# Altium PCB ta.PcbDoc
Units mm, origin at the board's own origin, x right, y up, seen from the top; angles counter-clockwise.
Board outline 41.15 x 64.9 mm, 2 copper layers (Top Layer, Bottom Layer); 9 components, 15 nets, 58 pads, 0 vias.
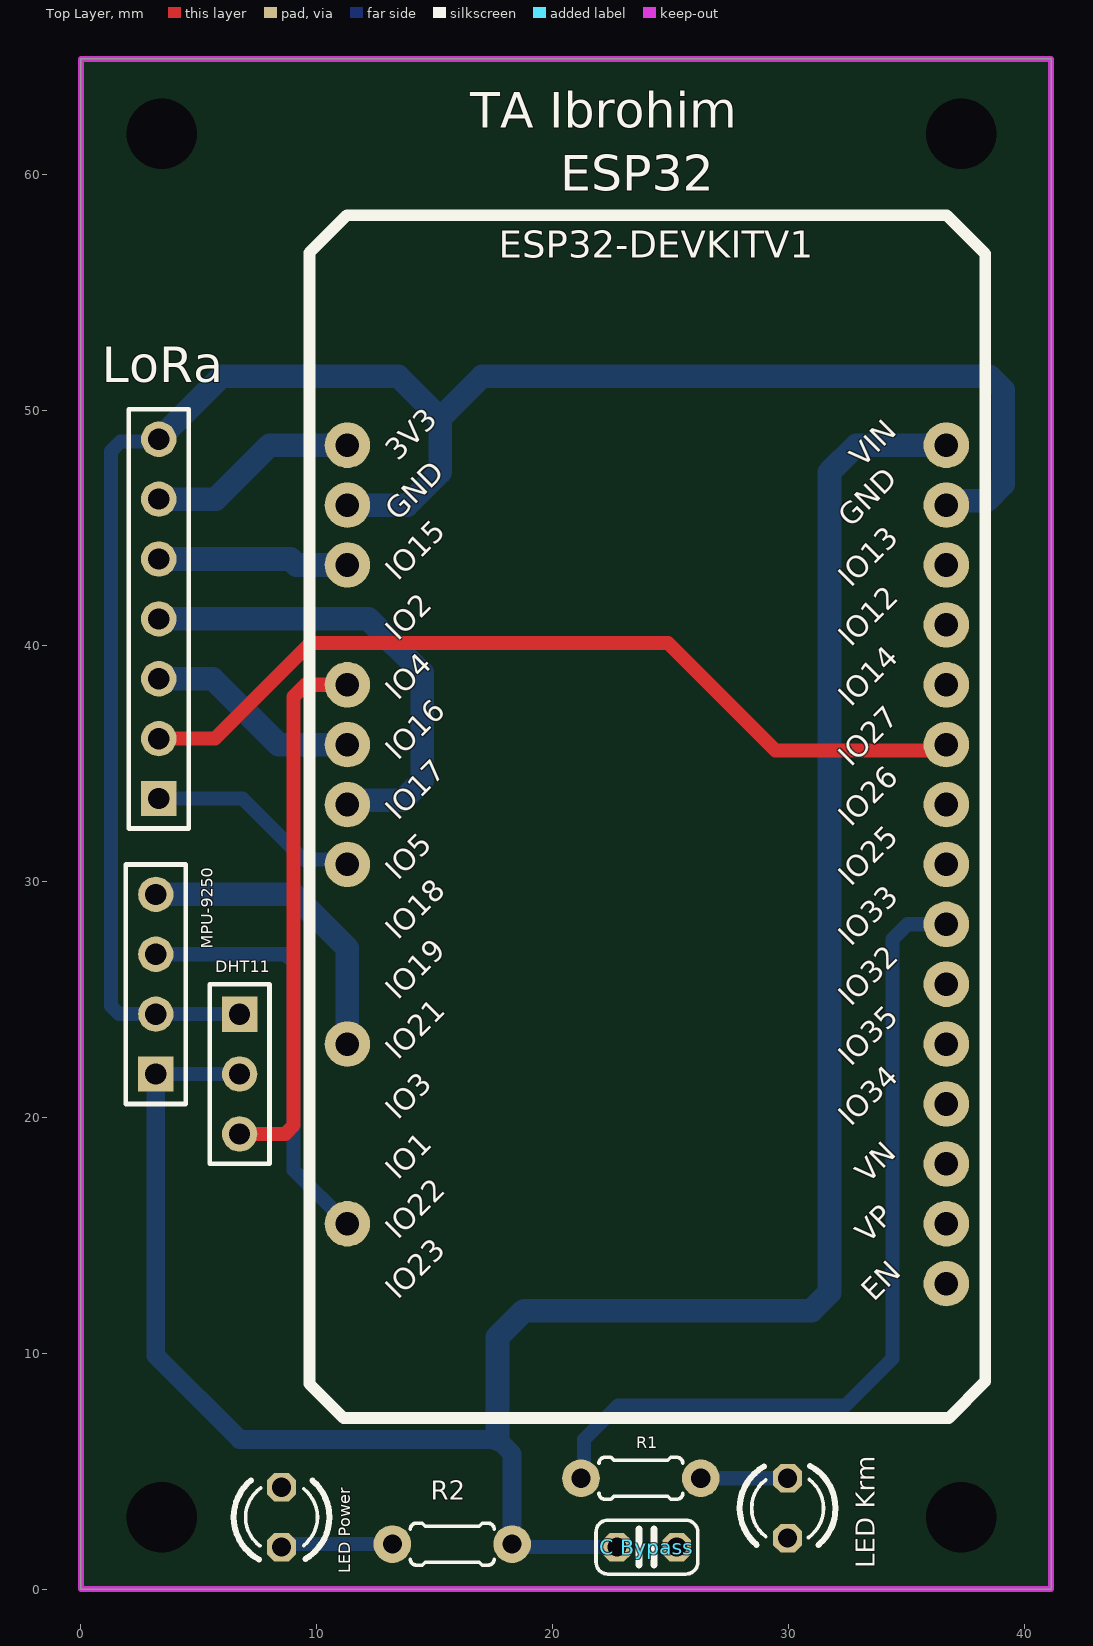
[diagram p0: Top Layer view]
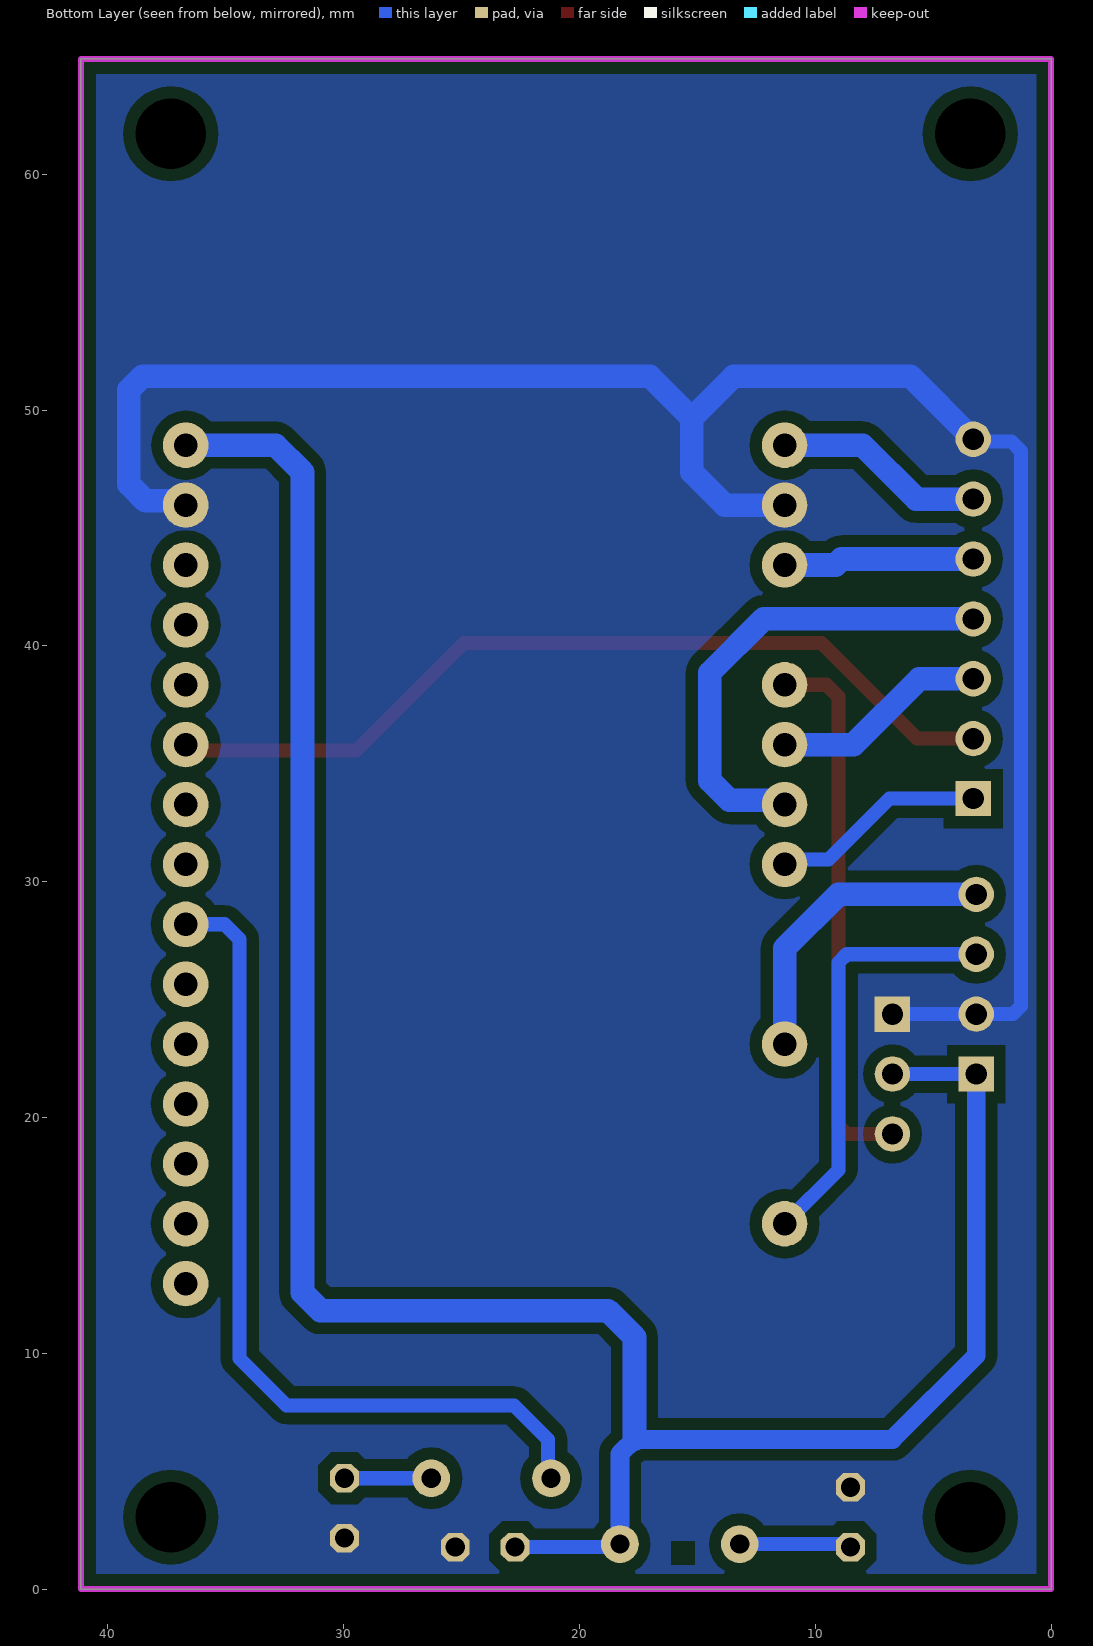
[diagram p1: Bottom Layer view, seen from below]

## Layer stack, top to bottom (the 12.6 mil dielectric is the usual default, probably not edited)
Top Solder: solder mask 0.0102, Solder Resist, Dk 3.5
Top Layer: signal copper 0.0356
Dielectric 1: dielectric 0.32, FR-4, Dk 4.8
Bottom Layer: signal copper 0.0356
Bottom Solder: solder mask 0.0102, Solder Resist, Dk 3.5

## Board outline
0,0 41.148,0 41.148,64.897 0,64.897

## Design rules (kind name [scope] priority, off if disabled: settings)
Clearance [All] p1: gap=0.5 ignorepadtopadclearanceinfootprint=FALSE
HoleSize [All] p1: absolutevalues=TRUE maxlimit=3 minlimit=0.025 maxpercent=80.000 minpercent=20.000
PlaneConnect [All] p1: planeconnectstyle=Direct reliefexpansion=0.508 reliefentries=4 reliefconductorwidth=0.254 reliefairgap=0.254
PolygonConnect [All] p1: connectstyle=Direct reliefconductorwidth=0.254 reliefentries=4 polygonreliefangle="90 Angle" airgapwidth=0.254
RoutingVias [All] p1: holewidth=0.711 width=1.27 viastyle="Through Hole" minholewidth=0.711 minwidth=1.27 maxholewidth=0.711 maxwidth=1.27
SilkToSilkClearance [All] p1: silktosilkclearance=0.104
SilkToSolderMaskClearance [IsPad] p1: minsilkscreentomaskgap=0.104 clearancetoexposedcopper=TRUE
SolderMaskExpansion [All] p1: expansion=0.102 istentingtop=FALSE
Width [All] p1: maxlimit=1.5 minlimit=0.5 preferedwidth=1
26 further rules are at their usual default settings.

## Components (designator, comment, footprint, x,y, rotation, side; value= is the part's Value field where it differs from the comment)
"C Bypass" "100nF" C025-024X044 24.003,1.778 r180 top
DHT11 "DHT11" HDR1X3 6.731,24.384 r270 top
ESP32 "ESP32-DEVKITC-32D" MODULE_ESP32-DEVKITV1 24.003,33.514 r0 top
"LED Krm" "LED Radial" LED3MM 29.972,3.429 r270 top (schematic designator "LED Kirim")
"LED Power" "LED Radial" LED3MM 8.509,3.048 r90 top
LoRa "Header 7" HDR1X7 3.302,33.528 r90 top
MPU-9250 "Header 4" HDR1X4 3.175,21.844 r90 top
R1 "330" 0204/5 23.749,4.699 r0 top
R2 "330" 0204/5 15.748,1.905 r180 top

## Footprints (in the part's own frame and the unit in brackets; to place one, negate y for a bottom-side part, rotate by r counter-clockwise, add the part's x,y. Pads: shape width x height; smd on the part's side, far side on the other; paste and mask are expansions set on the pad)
0204/5 [mm]
  round 1.6 hole 0.813: 1(-2.54,0) 2(2.54,0)
  silkscreen extent -1.78,-0.89 1.78,0.89, body extent -3.22,-0.88 3.23,0.89, height 1.76
C025-024X044 [mil]
  oct 48x48 hole 32: 1(-50,0) 2(50,0)
  silkscreen extent -85,-45 85,45, body extent -93,-49 93,49, height 242
HDR1X3 [mm] "Connector; Header; 3 Position"
  rect 1.5x1.5 hole 0.9: 1(0,0)
  round 1.5 hole 0.9: 2(2.54,0) 3(5.08,0)
  silkscreen extent -1.27,-1.27 6.35,1.27
HDR1X4 [mm] "Connector; Header; 4 Position"
  rect 1.5x1.5 hole 0.9: 1(0,0)
  round 1.5 hole 0.9: 2(2.54,0) 3(5.08,0) 4(7.62,0)
  silkscreen extent -1.27,-1.27 8.89,1.27
HDR1X7 [mm] "Connector; Header; 7 Position"
  rect 1.5x1.5 hole 0.9: 1(0,0)
  round 1.5 hole 0.9: 2(2.54,0) 3(5.08,0) 4(7.62,0) 5(10.16,0) 6(12.7,0) 7(15.24,0)
  silkscreen extent -1.27,-1.27 16.51,1.27
LED3MM [mil]
  oct 48x48 hole 32: 1(-50,0) 2(50,0)
  silkscreen extent -71,-80 61,80
MODULE_ESP32-DEVKITV1 [mil]
  round 76 / inner round 60 / far side round 76 hole 39.37: 1(-500,590.55) 2(-500,490.55) 3(-500,390.55) 6(-500,90.55) 7(-500,-9.45) 11(-500,-409.45) 14(-500,-709.45) 16(500,-809.45) 17(500,-709.45) 18(500,-609.45) 19(500,-509.45) 20(500,-409.45) 21(500,-309.45) 22(500,-209.45) 23(500,-109.45) 24(500,-9.45) 25(500,90.55) 26(500,190.55) 27(500,290.55) 28(500,390.55) 29(500,490.55) 30(500,590.55)
  round 76 on Top Paste: 4(-500,290.55) 9(-500,-209.45) 10(-500,-309.45) 15(-500,-809.45)
  round 76 hole 39.37: 5(-500,190.55) 8(-500,-109.45)
  round 0 all layers, no hole: 12(-500,-509.45) 13(-500,-609.45)
  silkscreen extent -563,-1034 565,974, body extent -560,-1027 562,978, height 283

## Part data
"C Bypass": library part Cap, "Cap Nonpolar (Pad-length X width)"
DHT11: library part "Header 3", "Header, 3-Pin"
ESP32: "Eval Board For Esp-Wroom-32", Package=None
LoRa: "Header, 7-Pin"
MPU-9250: "Header, 4-Pin"
R1 R2: library part "Res 0204", "Resistor 0204"

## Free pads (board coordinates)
  round 0 hole 3: 2(3.429,3.048) 3(37.338,3.048) 4(37.338,61.722) 5(3.429,61.722)

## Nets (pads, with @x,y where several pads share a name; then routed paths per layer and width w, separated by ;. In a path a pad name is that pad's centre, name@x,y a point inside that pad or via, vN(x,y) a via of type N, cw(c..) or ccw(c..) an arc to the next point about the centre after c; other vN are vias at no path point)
3v: ESP32.1 LoRa.6 | length 9.1
  Bottom Layer w1: LoRa.6@3.393,46.137 LoRa.6 5.715,46.228 8.001,48.514 ESP32.1 ESP32.1@11.352,48.465
AUX: ESP32.3 LoRa.5 | length 8.2
  Bottom Layer w1: LoRa.5 8.89,43.688 9.144,43.434 ESP32.3 ESP32.3@11.251,43.486
D13: ESP32.28
GND: "C Bypass.1" "LED Krm.2" "LED Power.2" DHT11.1 ESP32.2 ESP32.29 LoRa.7 MPU-9250.2 | length 83.8
  Bottom Layer w0.6: 3.13,36.24 3.302,36.068 ; LoRa.7@3.206,48.672 1.682,48.672 1.27,48.26 1.27,24.735 1.621,24.384 DHT11.1
  Bottom Layer w1: LoRa.7@3.206,48.672 LoRa.7 5.969,51.435 13.462,51.435 15.24,49.657 ; ESP32.2 13.843,45.974 15.24,47.371 15.24,49.657 ; ESP32.29 36.881,46.152 38.405,46.152 39.116,46.863 39.116,50.854 38.53,51.44 17.023,51.44 15.24,49.657
M0: ESP32.8 LoRa.1 | length 9.2
  Bottom Layer w0.6: LoRa.1 6.858,33.528 9.438,30.948 11.089,30.948 ESP32.8
M1: ESP32.25 LoRa.2 | length 37.1
  Top Layer w0.6: LoRa.2 5.683,36.068 9.735,40.119 24.905,40.119 29.464,35.56 36.449,35.56 ESP32.25
NetESP32_22: ESP32.22 R1.1 | length 36.5
  Bottom Layer w0.6: R1.1 21.336,4.826 21.336,6.35 22.776,7.79 32.428,7.79 34.417,9.779 34.417,27.559 35.052,28.194 ESP32.22
"NetLED Krm_1": "LED Krm.1" R1.2 | length 3.7
  Bottom Layer w0.6: R1.2 29.972,4.699
"NetLED Power_1": "LED Power.1" R2.2 | length 4.9
  Bottom Layer w0.6: 8.69,1.597 8.509,1.778 8.636,1.905 12.954,1.905 R2.2@13.081,2.032
RX: ESP32.6 LoRa.3 | length 9.3
  Bottom Layer w1: LoRa.3@3.393,38.517 LoRa.3 5.588,38.608 8.382,35.814 ESP32.6
SCL: ESP32.14 MPU-9250.3 | length 18
  Bottom Layer w0.6: MPU-9250.3 8.666,26.924 9.017,26.573 9.017,17.78 ESP32.14
SDA: ESP32.11 MPU-9250.4 | length 13.1
  Bottom Layer w1: MPU-9250.4 9.017,29.464 11.303,27.178 ESP32.11
SIG: DHT11.3 ESP32.5 | length 23.5
  Top Layer w0.6: DHT11.3 8.666,19.304 9.017,19.655 9.017,37.846 9.525,38.354 ESP32.5
  Bottom Layer w0.6: ESP32.5@10.951,38.354 ESP32.5
TX: ESP32.7 LoRa.4 | length 20.6
  Bottom Layer w1: LoRa.4@3.206,41.244 LoRa.4 12.192,41.148 14.478,38.862 14.478,34.29 13.64,33.452 11.481,33.452 ESP32.7 ESP32.7@11.43,33.147
VCC: "C Bypass.2" DHT11.2 ESP32.30 MPU-9250.1 R2.1 | length 100.1
  Bottom Layer w0.6: MPU-9250.1 DHT11.2 ; R2.1 18.415,1.778 22.733,1.778
  Bottom Layer w0.8: MPU-9250.1 3.175,9.906 6.731,6.35 17.669,6.35 18.288,5.731 R2.1
  Bottom Layer w1: 17.669,6.35 17.669,10.684 18.796,11.811 30.988,11.811 31.75,12.573 31.75,47.371 32.893,48.514 ESP32.30
pads on no net: ESP32.4 ESP32.9 ESP32.10 ESP32.12 ESP32.13 ESP32.15 ESP32.16 ESP32.17 ESP32.18 ESP32.19 ESP32.20 ESP32.21 ESP32.23 ESP32.24 ESP32.26 ESP32.27

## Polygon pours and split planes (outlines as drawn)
GND on Bottom Layer "Bottom Layer-No Net" (solid, remove dead copper, pour order 38): 0,0 41.148,0 41.148,64.897 0,64.897
GND on Bottom Layer "GND_L02_P031" (solid, pour order 31): 1.143,24.892
GND on Bottom Layer "GND_L02_P019" (solid, pour order 19): 2.032,25.019
GND on Bottom Layer "GND" (solid, pour order 4): 13.037,51.932 17.156,51.932 17.272,51.816 15.621,50.165 14.859,50.165 13.208,51.816 13.081,51.816
no net on Bottom Layer "NONET_L02_P001" (solid, pour order 1): 0.97,25.187
no net on Bottom Layer "NONET_L02_P000" (solid, pour order 0): 1.651,23.749

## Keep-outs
Keep-Out Layer:
  the board outline again, w0.254

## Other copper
Bottom Layer:

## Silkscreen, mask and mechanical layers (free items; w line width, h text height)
Top Overlay:
  text "TA Ibrohim" at 16.51,61.976 h1.52

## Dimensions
41.148,64.897 to 41.148,0 on Top Overlay
0,64.897 to 41.148,64.897 on Top Overlay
